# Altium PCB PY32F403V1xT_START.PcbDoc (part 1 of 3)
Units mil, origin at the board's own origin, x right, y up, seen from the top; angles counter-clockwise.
Board outline 1968.43 x 4717 mil, 2 copper layers (Top Layer, Bottom Layer), stack 21 mil thick; 171 components, 201 nets, 720 pads, 402 vias.
Unrouted connection lines stored in the file: 1.
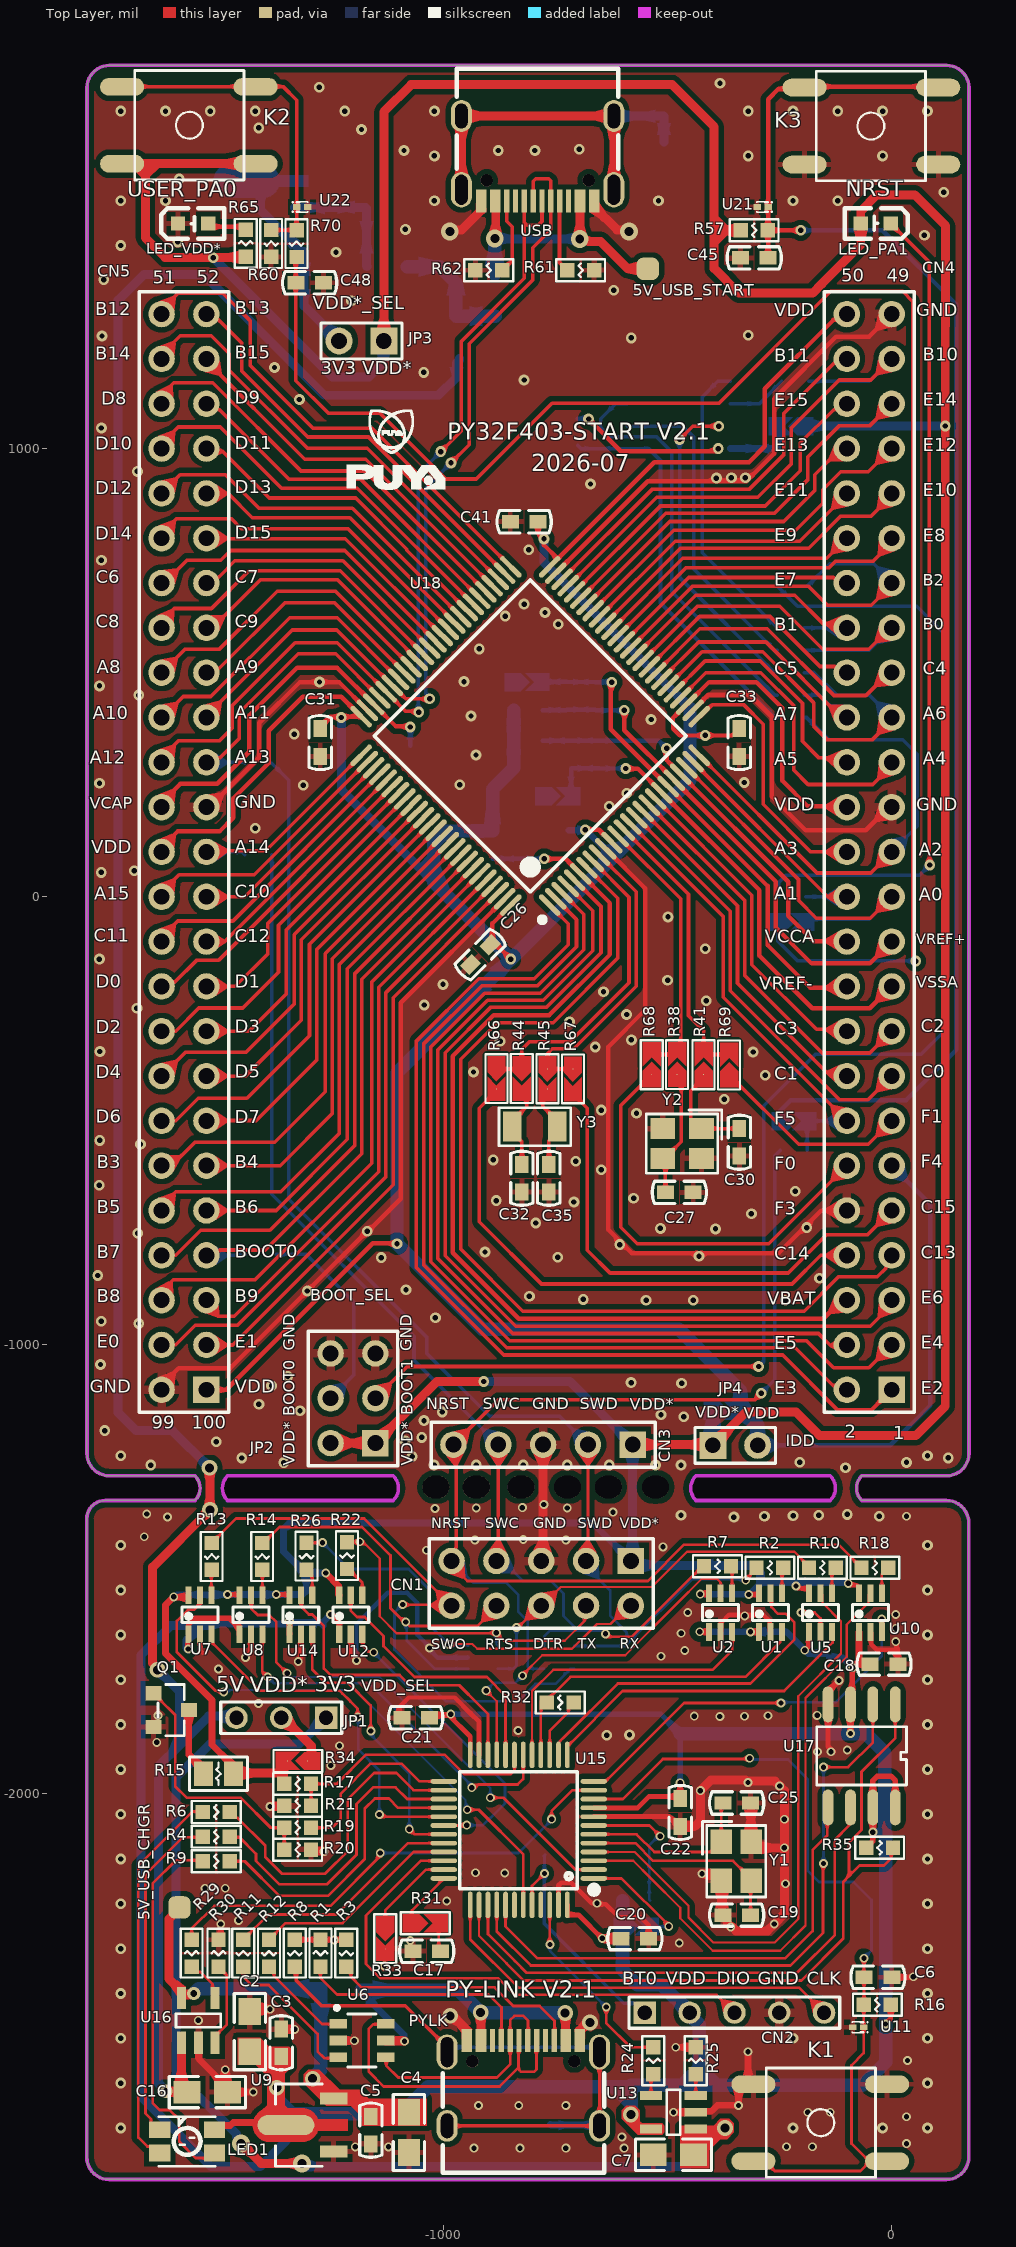
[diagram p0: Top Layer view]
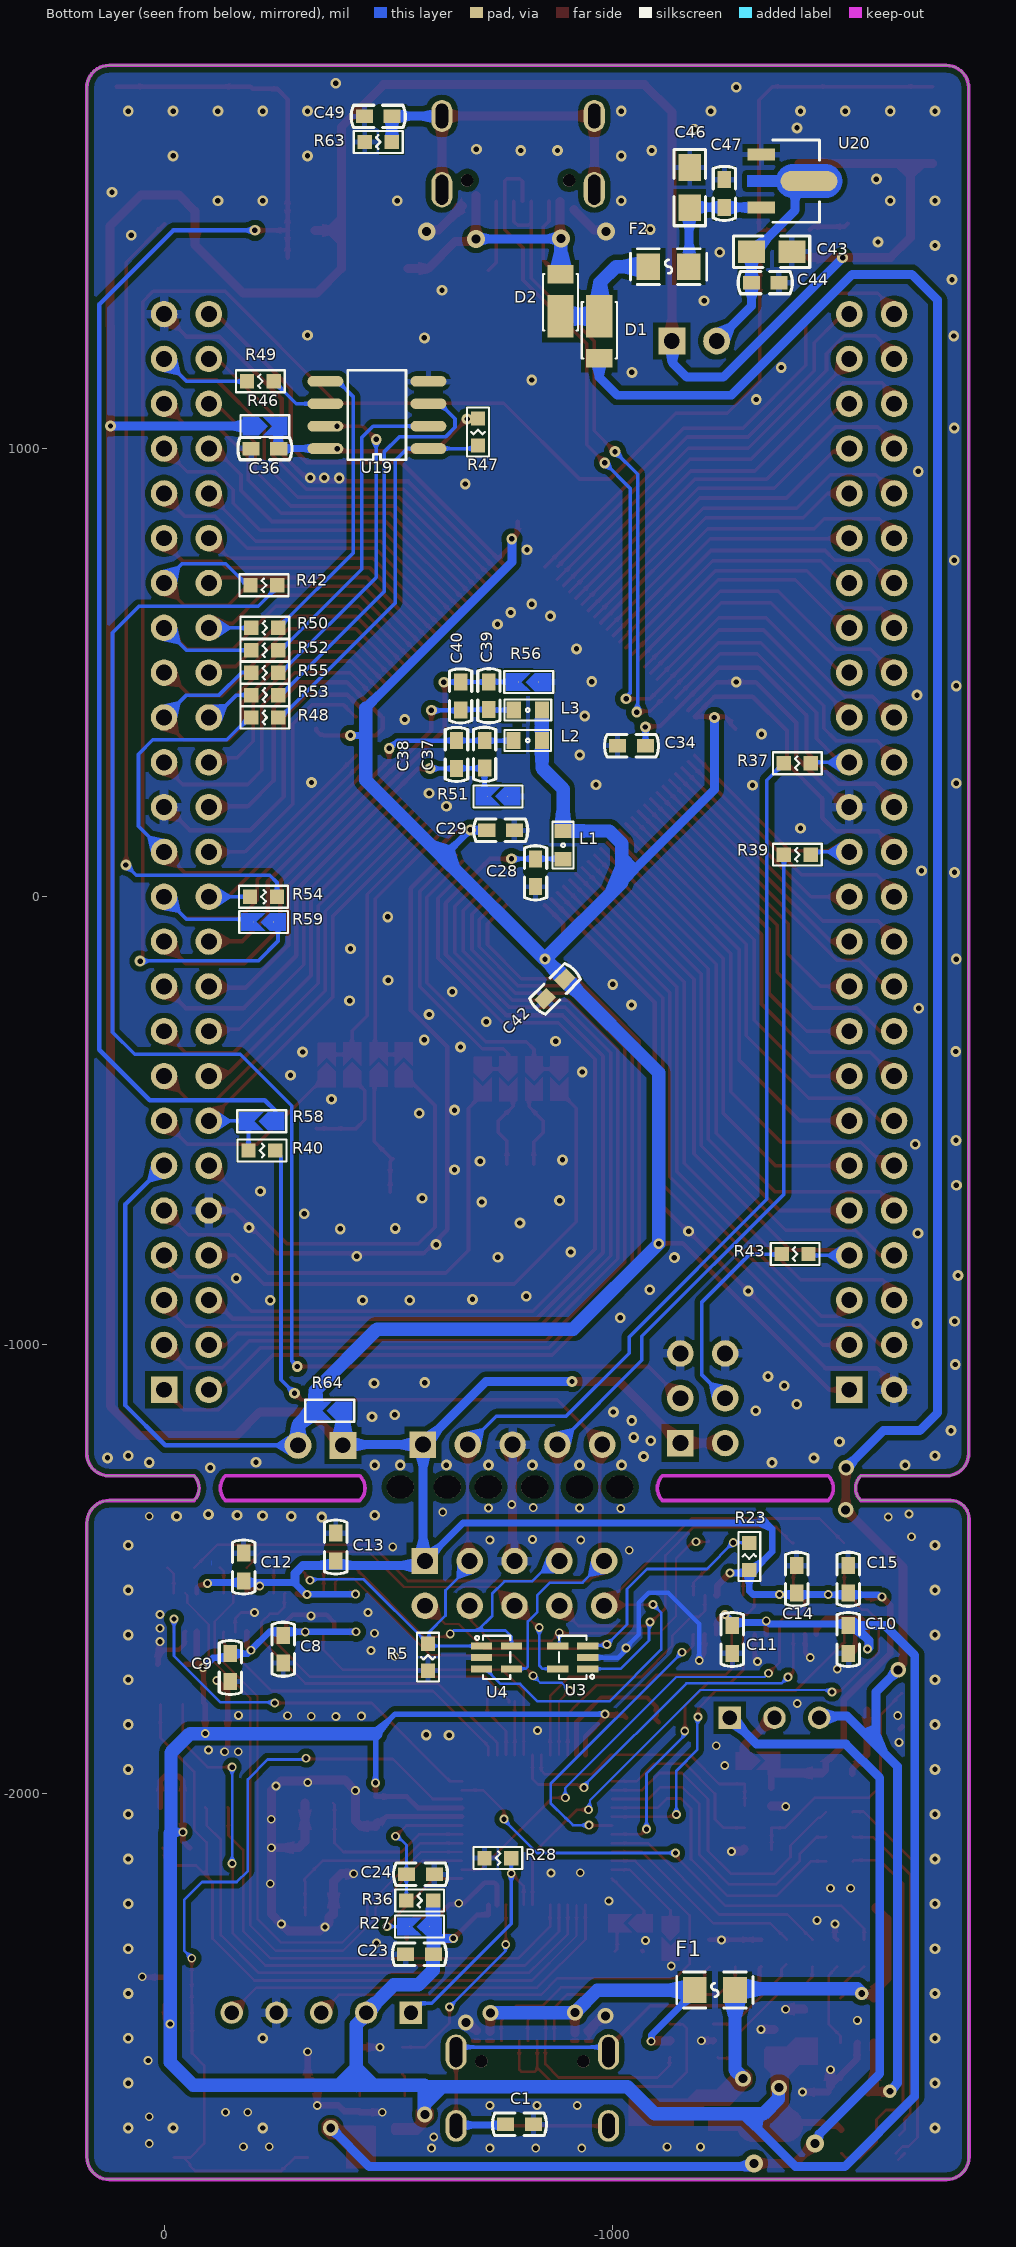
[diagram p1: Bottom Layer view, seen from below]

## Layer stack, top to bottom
Top Solder: solder mask 0.4, Solder Resist, Dk 3.5
Top Layer: signal copper 1.4
Dielectric 2: prepreg 2.8, Composite dielectric, Dk 4.1
Dielectric 1: prepreg 12.6, Composite dielectric, Dk 4.1
Dielectric 3: prepreg 2.8, Composite dielectric, Dk 4.1
Bottom Layer: signal copper 1.4
Bottom Solder: solder mask 0.4, Solder Resist, Dk 3.5

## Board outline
-1796,-2812 ccw(c-1746,-2812) -1746,-2862 122,-2862 ccw(c122,-2812) 172,-2812 172,-1397 ccw(c122,-1397) 122,-1347 -67,-1347 cw(c-39.5,-1319.5) -67,-1292 122.43,-1292 ccw(c122.43,-1242) 172.43,-1242 172.43,1805 ccw(c122.43,1805) 122.43,1855 -1745.43,1855 ccw(c-1745.43,1805) -1795.43,1805 -1795.43,-1242 ccw(c-1745.43,-1242) -1745.43,-1292 -1554.5,-1292 cw(c-1582,-1319.5) -1554.5,-1347 -1755,-1347 ccw(c-1755,-1388) -1796,-1388
cut-out: -437,-1347 cw(c-409.5,-1319.5) -437,-1292 -137,-1292 cw(c-164.5,-1319.5) -137,-1347
cut-out: -1482,-1347 cw(c-1454.5,-1319.5) -1482,-1292 -1112,-1292 cw(c-1139.5,-1319.5) -1112,-1347
cut-out: -1482,-1347 cw(c-1454.5,-1319.5) -1482,-1292 -1112,-1292 cw(c-1139.5,-1319.5) -1112,-1347 -1132,-1347
cut-out: -437,-1347 cw(c-409.5,-1319.5) -437,-1292 -137,-1292 cw(c-164.5,-1319.5) -137,-1347

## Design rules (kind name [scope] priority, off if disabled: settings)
Clearance polygon [InPolygon] p1: gap=12 ignorepadtopadclearanceinfootprint=TRUE
Clearance [All] p2: gap=8 ignorepadtopadclearanceinfootprint=TRUE
HoleToHoleClearance [All] p1: gap=1 allowstackedmicrovias=TRUE
MinimumSolderMaskSliver [All] p1: minsoldermaskwidth=0
PlaneClearance [All] p1: clearance=8
PlaneConnect [All] p1: planeconnectstyle=Direct reliefexpansion=20 reliefentries=4 reliefconductorwidth=10 reliefairgap=10
PolygonConnect [All] p1: thpad.connectstyle=Relief thpad.reliefconductorwidth=20 thpad.reliefentries=4 thpad.polygonreliefangle="90 Angle" thpad.airgapwidth=10 smdpad.connectstyle=Relief smdpad.reliefconductorwidth=12 smdpad.reliefentries=4 smdpad.polygonreliefangle="90 Angle" smdpad.airgapwidth=10 via.connectstyle=Direct via.reliefconductorwidth=10 via.reliefentries=4 via.polygonreliefangle="90 Angle" via.airgapwidth=10
RoutingVias [All] p1: holewidth=28 width=50 viastyle="Through Hole" minholewidth=28 minwidth=50 maxholewidth=28 maxwidth=50
SilkToSilkClearance [All] p1: silktosilkclearance=0
SilkToSolderMaskClearance [IsPad] p1: minsilkscreentomaskgap=0 clearancetoexposedcopper=TRUE
SolderMaskExpansion [All] p1: expansion=4 istentingtop=FALSE
UnRoutedNet [All] p1: checkbadconnections=TRUE
Width [All] p1: maxlimit=100 minlimit=5 preferedwidth=8
23 further rules are at their usual default settings.

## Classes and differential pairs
component class PY32F403V1xT_START: 5V_USB_START C26 C27 C28 C29 C30 C31 C32 C33 C34 C35 C36 C37 C38 C39 C40 C41 C42 C43 C44 C45 C46 C47 C48 C49 CN3 CN4 CN5 D1 D2 F2 "IDD Test" JP2 JP3 JP4 K2 K3 L1 L2 L3 LED_PA1 LED_VDD* PF8 R37 R38 R39 R40 R41 R42 R43 R44 R45 R46 R47 R48 R49 R50 R51 R52 R53 R54 R55 R56 R57 R58 R59 R60 R61 R62 R63 R64 R65 R66 R67 R68 R69 R70 ss U18 U19 U20 U21 U22 USB Y2 Y3
component class PY32F403C1xT_LINK: 5V_USB_CHGR C1 C2 C3 C4 C5 C6 C7 C8 C9 C10 C11 C12 C13 C14 C15 C16 C17 C18 C19 C20 C21 C22 C23 C24 C25 CN1 CN2 F1 JP1 K1 LED1 PYLK Q1 R1 R2 R3 R4 R5 R6 R7 R8 R9 R10 R11 R12 R13 R14 R15 R16 R17 R18 R19 R20 R21 R22 R23 R24 R25 R26 R27 R28 R29 R30 R31 R32 R33 R34 R35 R36 ss U1 U2 U3 U4 U5 U6 U7 U8 U9 U10 U11 U12 U13 U14 U15 U16 U17 Y1

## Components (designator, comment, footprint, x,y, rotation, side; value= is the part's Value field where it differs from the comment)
5V_USB_CHGR "TP_SIN" TP_SIN -1589,-2255 r90 top
5V_USB_START "TP_SIN" TP_SIN -544,1401 r90 top
C1 "4.7nF" C0603 -793,-2739 r0 bottom
C2 "10uF" C0805 -1432,-2532 r270 top
C3 "100nF" C0603 -1362,-2557 r270 top
C4 "10uF" C0805 -1077,-2757 r90 top
C5 "100nF" C0603 -1162,-2752 r90 top
C6 "100nF" C0603 -30.8,-2410.8 r180 top
C7 "10uF" C0805 -487,-2807 r0 top
C8 "100nF" C0603 -266,-1679 r90 bottom value=104
C9 "100nF" C0603 -148.1,-1719.7 r90 bottom value=104
C10 "100nF" C0603 -1526.8,-1657.1 r90 bottom value=104
C11 "100nF" C0603 -1268,-1657.1 r90 bottom value=104
C12 "100nF" C0603 -177.6,-1495.4 r270 bottom value=104
C13 "100nF" C0603 -383.2,-1450.9 r270 bottom value=104
C14 "100nF" C0603 -1411.5,-1522.8 r270 bottom value=104
C15 "100nF" C0603 -1526.5,-1522.8 r270 bottom value=104
C16 "10uF" C0805 -1527,-2667 r180 top
C17 "100nF" C0603 -1037.41,-2352.5 r0 top
C18 "100nF" C0603 -17,-1712 r180 top value=104
C19 "22pF" C0603 -345.88,-2272 r0 top
C20 "100nF" C0603 -573.13,-2324.41 r180 top value=104
C21 "100nF" C0603 -1062,-1832 r0 top value=104
C22 "100nF" C0603 -471.88,-2043 r90 top value=104
C23 "100nF" C0603 -569.9,-2359.7 r180 bottom value=104
C24 "100nF" C0603 -572.5,-2181.2 r0 bottom value=104
C25 "22pF" C0603 -345.88,-2022 r180 top
C26 "100nF" c0603cap -939.9,-151.1 r135 top
C27 "22pF" C0603 -473.8,-659.7 r180 top
C28 "100nF" c0603cap -828.9,22.4 r0 bottom
C29 "100nF" c0603cap -782.1,148.2 r270 bottom
C30 "22pF" C0603 -339.8,-547.7 r90 top
C31 "100nF" c0603cap -1275,375 r0 top
C32 "22pF" C0603 -825,-628 r270 top
C33 "100nF" c0603cap -340,375 r0 top
C34 "100nF" c0603cap -1074.1,337.1 r270 bottom
C35 "22pF" C0603 -765,-628 r90 top
C36 "100nF" C0603 -225,1000 r180 bottom value=104
C37 "1uF" C0603 -715.2,317.8 r90 bottom
C38 "100nF" C0603 -652.6,317.6 r90 bottom
C39 "1uF" C0603 -724.9,448.6 r270 bottom
C40 "100nF" C0603 -661.6,448.2 r270 bottom
C41 "100nF" c0603cap -851,837 r90 top
C42 "10uF" c0603cap -850.5,-227.5 r45 bottom
C43 "10uF" C0805 -1355.9,1439.4 r0 bottom
C44 "100nF" C0603 -1341.5,1370.3 r0 bottom
C45 "100nF" C0603 -306.7,1425.3 r0 top
C46 "10uF" C0805 -1173,1582.3 r270 bottom
C47 "100nF" C0603 -1250.3,1569.4 r270 bottom
C48 "100nF" C0603 -1298.6,1369.9 r180 top
C49 "4.7nF" C0603 -478,1741 r180 bottom
CN1 "2X5P" HDR2X5 -582,-1482 r180 top
CN2 "CON5" CON5 -550.9,-2489.7 r0 top
CN3 "Header 5" HDR1X5 -577.74,-1222.44 r180 top
CN4 "2X25P" HDR2X25 0,-1100 r90 top
CN5 "2X25P" HDR2X25 -1529,-1100 r90 top
D1 "DFLS130L-7" POWERDI-123_L2.8-W1.8-LS3.7-RD -971.3,1248.6 r270 bottom
D2 "DFLS130L-7" POWERDI-123_L2.8-W1.8-LS3.7-RD -884.6,1342.3 r90 bottom
F1 "JK-SMD0805-050-16V" F0805 -1229,-2439.2 r180 bottom
F2 "JK-SMD0805-050-16V" F0805 -1125.7,1406 r180 bottom
JP1 "CON3" CON3 -1262,-1832 r180 top
JP2 "Header 3X2" HDR2X3 -1152,-1219 r90 top
JP3 "CON2" CON2 -1133,1240 r180 top
JP4 "CON2" CON2 -399,-1224 r0 top
K1 "TS-KG02S-AT43F" SW-SMD_4P-L6.0-W6.0-P4.50-LS8.5 -157.4,-2735.5 r180 top
K2 "TS-KG02S-AT43F" SW-SMD_4P-L6.0-W6.0-P4.50-LS8.5 -1566.2,1721.2 r180 top
K3 "TS-KG02S-AT43F" SW-SMD_4P-L6.0-W6.0-P4.50-LS8.5 -47.2,1719.8 r0 top
L1 "GZ1608D601TF" L0603 -890.4,115.2 r90 bottom value=600R@100MHz
L2 "GZ1608D601TF" L0603 -811.6,348.8 r0 bottom value=600R@100MHz
L3 "GZ1608D601TF" L0603 -811.8,416.6 r0 bottom value=600R@100MHz
LED1 "MHPA3528RGBCT" LED-ARRAY-SMD_4P-L3.5-W2.8-TL -1572,-2777 r0 top
LED_PA1 "GREEN" 0603_LED -50,1503 r180 top
LED_VDD* "RED" 0603_LED -1544,1501 r0 top
PYLK "KH-TYPE-C-16P" USB-C-SMD_KH-TYPE-C-16P -821.8,-2647.19 r0 top locked
Q1 "2302" SOT23 -1607.63,-1814.6 r90 top value=SI2302
R1 "5.1K" R0603 -1274.51,-2357.01 r270 top
R2 "27R" R0603 -271.79,-1497 r180 top
R3 "5.1K" R0603 -1217,-2357 r90 top
R4 "680R" R0603 -1507,-2097 r0 top
R5 "1M" R0603 -589.1,-1696.6 r90 bottom
R6 "680R" R0603 -1507,-2042 r0 top
R7 "27R" R0603 -388.61,-1493.9 r180 top
R8 "1M" R0603 -1332,-2357 r90 top
R9 "680R" R0603 -1507,-2152 r0 top
R10 "27R" R0603 -154.65,-1497 r180 top
R11 "27R" R0603 -1447,-2357 r90 top
R12 "27R" R0603 -1389.5,-2357 r90 top
R13 "27R" R0603 -1517.34,-1471.92 r90 top
R14 "27R" R0603 -1404.7,-1471.9 r90 top
R15 "100R" R0805 -1502,-1957 r0 top
R16 "10K" R0603 -32,-2472 r0 top
R17 "20K" R0603 -1325.48,-1979.39 r180 top
R18 "27R" R0603 -37.51,-1497 r180 top
R19 "100R" R0603 -1325.47,-2077.22 r0 top
R20 "100K" R0603 -1325.48,-2126.12 r180 top
R21 "10K" R0603 -1325.47,-2028.31 r0 top
R22 "27R" R0603 -1215.37,-1469.89 r90 top
R23 "4.7K" R0603 -1306,-1472 r270 bottom
R24 "4.7K" R0603 -532,-2597 r270 top
R25 "16K" R0603 -437,-2597 r270 top
R26 "27R" R0603 -1305.8,-1471.3 r90 top
R27 "0R" JP2_SMD -570,-2297.6 r180 bottom
R28 "10K" R0603 -745,-2144.92 r0 bottom
R29 "4.7K" R0603 -1562,-2357 r270 top
R30 "16K" R0603 -1502,-2357 r270 top
R31 "0R" JP2_SMD -1040.79,-2290.25 r180 top
R32 "680R" R0603 -739.54,-1797.63 r0 top
R33 "0R" JP2_SMD -1130.04,-2324.6 r90 top
R34 "0R" JP2_SMD -1325,-1928.2 r0 top
R35 "100K" R0603 -27,-2122 r180 top
R36 "10K" R0603 -570.4,-2239.5 r180 bottom
R37 "100R" R0603 -1413.09,298 r180 bottom
R38 "0R" JP2_SMD -478.8,-374.69 r270 top
R39 "100R" R0603 -1413.09,94 r180 bottom
R40 "0R" R0603 -218.55,-566 r0 bottom
R41 "0R" JP2_SMD -419.8,-374.7 r270 top
R42 "10K" R0603 -223,695 r180 bottom
R43 "10K" R0603 -1408,-797 r180 bottom
R44 "0R" JP2_SMD -825.5,-405.6 r90 top
R45 "0R" JP2_SMD -768,-406 r90 top
R46 "0R" JP2_SMD -224.9,1050.1 r0 bottom
R47 "100K" R0603 -700.5,1037 r90 bottom
R48 "0R" R0603 -225,400 r180 bottom
R49 "0R" R0603 -215,1150 r180 bottom
R50 "0R" R0603 -225,600 r180 bottom
R51 "0R" JP2_SMD -745.1,223.9 r180 bottom
R52 "0R" R0603 -225,550 r180 bottom
R53 "0R" R0603 -225,450 r180 bottom
R54 "1K" R0603 -222,0 r0 bottom
R55 "0R" R0603 -225,500 r180 bottom
R56 "0R" JP2_SMD -813.7,479.1 r180 bottom
R57 "10K" R0603 -306.8,1486.9 r0 top
R58 "0R" JP2_SMD -218,-500.9 r180 bottom
R59 "0R" JP2_SMD -222.3,-56.3 r180 bottom
R60 "1.5K" R0603 -1384.6,1457.7 r90 top
R61 "5.1K" R0603 -694,1398 r0 top
R62 "5.1K" R0603 -899,1398 r0 top
R63 "1M" R0603 -478,1684 r180 bottom
R64 "0R" JP2_SMD -369.8,-1146.6 r180 bottom
R65 "680R" R0603 -1441,1458 r270 top
R66 "0R" JP2_SMD -881.77,-405.67 r90 top
R67 "0R" JP2_SMD -711.1,-406.15 r90 top
R68 "0R" JP2_SMD -535.3,-374.7 r270 top
R69 "0R" JP2_SMD -362.9,-375.25 r270 top
R70 "330R" R0603 -1327.8,1457.3 r90 top
U1 "74LVC1T45DW" SOT363 -270.36,-1597 r0 top
U2 "74LVC1T45DW" SOT363 -381.79,-1597 r0 top
U3 "ESD_6V1" ESD_SOT323-5L -912,-1697 r90 bottom value=ESDALC6V1W5
U4 "ESD_6V1" ESD_SOT323-5L -742,-1697 r270 bottom value=ESDALC6V1W5
U5 "74LVC1T45DW" SOT363 -158.94,-1597 r0 top locked
U6 "USBLC6-2SC6" SOT23-6 -1182,-2552 r90 top
U7 "74LVC1T45DW" SOT363 -1543.45,-1602 r0 top locked
U8 "74LVC1T45DW" SOT363 -1429.74,-1602 r0 top
U9 "LM1117F-3.3" SOT-89-3_L4.5-W2.5-P1.50-LS4.2-BR -1298.2,-2740.6 r0 top
U10 "74LVC1T45DW" SOT363 -47.51,-1597 r0 top
U11 "ESDALC6V1-1U2" ESD_ST0201 -74.7,-2522.3 r180 top
U12 "74LVC1T45DW" SOT363 -1206.88,-1602 r0 top
U13 "MT9700" SOT23-5 -487,-2712 r90 top
U14 "74LVC1T45DW" SOT363 -1318.31,-1602 r0 top
U15 "PY32F403C1xT" LQFP-48_L7.0-W7.0-P0.50-LS9.0-BL -832,-2082 r90 top locked
U16 "MT9700" SOT23-5 -1547,-2507 r0 top
U17 "P25Q64SH" SOP-8P -67,-1917 r180 top value=SST25VF020B
U18 "PY32F403V1xT" LQFP-100_L14.0-W14.0-P0.50-LS16.0-BL -806.52,358.76 r45 top locked
U19 "P25Q64SH" SOP-8P -475,1075 r90 bottom value=SST25VF020B
U20 "LM1117F-3.3" SOT-89-3_L4.5-W2.5-P1.50-LS4.2-BR -1385.9,1596.8 r0 bottom
U21 "ESDALC6V1-1U2" ESD_ST0201 -288,1539 r180 top
U22 "ESDALC6V1-1U2" ESD_ST0201 -1315.3,1539 r0 top
USB "KH-TYPE-C-16P" USB-C-SMD_KH-TYPE-C-16P -790,1647 r180 top
Y1 "24MHz" CRYSTAL-SMD_4P-L3.2-W2.5-BL -346.88,-2152 r270 top
Y2 "24MHz" CRYSTAL-SMD_4P-L3.2-W2.5-BL -467.8,-550.7 r180 top
Y3 "32.768KHz" CRYSTAL-SMD_L3.2-W1.5-1 -796.2,-513.1 r0 top value=X503225MSB2GI

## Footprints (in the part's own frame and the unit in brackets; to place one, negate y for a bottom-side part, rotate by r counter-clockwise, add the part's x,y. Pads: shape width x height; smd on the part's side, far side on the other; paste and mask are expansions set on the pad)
0603_LED [mil]
  rect 31.5x31.5 smd: 1(19,1) 2(-48,1)
  silkscreen extent -86,-33 55,35
C0603 [mil]
  rect 38x30 smd: 1(-31,0) 2(31,0)
  silkscreen extent -60,-25 60,25
c0603cap [mil]
  rect 30x38 smd: 1(0,0) 2(0,-62)
  silkscreen extent -25,-91 25,29
C0805 [mil]
  rect 60x50 smd: 1(-45,0) 2(45,0)
  silkscreen extent -85,-35 85,35
CON2 [mil]
  rect 60x60 hole 35: 1(0,0)
  round 60 hole 35: 2(100,0)
  silkscreen extent -40,-40 140,40
CON3 [mil]
  rect 50x50 hole 32: 1(0,0)
  round 50 hole 32: 2(100,0) 3(200,0)
  silkscreen extent -35,-35 235,35
CON5 [mil]
  rect 50x50 hole 32: 1(0,0)
  round 50 hole 32: 2(100,0) 3(200,0) 4(300,0) 5(400,0)
  silkscreen extent -35,-35 435,35
CRYSTAL-SMD_4P-L3.2-W2.5-BL [mm]
  rect 1.4x1.2 smd: 1(-1.1,-0.85) 2(1.1,-0.85) 3(1.1,0.85) 4(-1.1,0.85)
  silkscreen extent -2.26,-1.91 2.03,1.68
CRYSTAL-SMD_L3.2-W1.5-1 [mm]
  rect 1.05x1.7 smd: 1(-1.275,0) 2(1.275,0)
  silkscreen extent -2.03,-1.08 2.03,1.08
ESD_SOT323-5L [mm]
  rect 0.4x1.2 smd mask+0.05: 1(-0.65,-0.85) 2(0,-0.85) 3(0.65,-0.85) 4(0.65,0.85) 5(-0.65,0.85)
  silkscreen extent -1.23,-1.21 1.23,0.77, body extent -1.15,-1.05 1.15,1.05, height 1.1
ESD_ST0201 [mm]
  rect 0.425x0.33 smd mask+0.05: 1(-0.312,0) 2(0.312,0)
  silkscreen extent -0.55,-0.3 0.33,0.3, body extent -0.34,-0.18 0.34,0.18, height 0.34
F0805 [mm]
  rect 1.335x1.5 smd paste-100 mask+0.051: 1(-1.142,0) 2(1.142,0)
  silkscreen extent -2.16,-1.02 2.16,1.02
HDR1X5 [mm] "Connector; Header; 5 Position"
  rect 1.5x1.5 hole 0.9: 1(0,0)
  round 1.5 hole 0.9: 2(2.54,0) 3(5.08,0) 4(7.62,0) 5(10.16,0)
  silkscreen extent -1.27,-1.27 11.43,1.27
HDR2X3 [mm] "Connector; Header; 3x2 Position"
  rect 1.5x1.5 hole 0.9: 1(0,0)
  round 1.5 hole 0.9: 2(0,2.54) 3(2.54,0) 4(2.54,2.54) 5(5.08,0) 6(5.08,2.54)
  silkscreen extent -1.27,-1.27 6.35,3.81
HDR2X5 [mm] "Connector; Header; 4x2 Position"
  rect 1.5x1.5 hole 0.9: 1(0,0)
  round 1.5 hole 0.9: 2(0,2.54) 3(2.54,0) 4(2.54,2.54) 5(5.08,0) 6(5.08,2.54) 7(7.62,0) 8(7.62,2.54) 9(10.16,0) 10(10.16,2.54)
  silkscreen extent -1.27,-1.27 11.43,3.81
HDR2X25 [mm] "Connector; Header; 25x2 Position"
  rect 1.5x1.5 hole 0.9: 1(0,0)
  round 1.5 hole 0.9: 2(0,2.54) 3(2.54,0) 4(2.54,2.54) 5(5.08,0) 6(5.08,2.54) 7(7.62,0) 8(7.62,2.54) 9(10.16,0) 10(10.16,2.54) 11(12.7,0) 12(12.7,2.54) 13(15.24,0) 14(15.24,2.54) 15(17.78,0) 16(17.78,2.54) 17(20.32,0) 18(20.32,2.54) 19(22.86,0) 20(22.86,2.54) 21(25.4,0) 22(25.4,2.54) 23(27.94,0) 24(27.94,2.54) 25(30.48,0) 26(30.48,2.54) 27(33.02,0) 28(33.02,2.54) 29(35.56,0) 30(35.56,2.54) 31(38.1,0) 32(38.1,2.54) 33(40.64,0) 34(40.64,2.54) 35(43.18,0) 36(43.18,2.54) 37(45.72,0) 38(45.72,2.54) 39(48.26,0) 40(48.26,2.54) 41(50.8,0) 42(50.8,2.54) 43(53.34,0) 44(53.34,2.54) 45(55.88,0) 46(55.88,2.54) 47(58.42,0) 48(58.42,2.54) 49(60.96,0) 50(60.96,2.54)
  silkscreen extent -1.27,-1.27 62.23,3.81
JP2_SMD [mil]
  round 1 smd: 1(21.75,0) 2(-23.03,0.03)
  Top Layer region: -6.25,0 13.75,20 49.75,20 49.75,-20 49.75,-20 13.75,-20
  Top Layer region: -49.77,20.03 -49.77,20.03 3.72,20.03 -16.28,0.03 3.72,-19.98 -49.78,-19.98 -49.78,-19.98
  silkscreen extent -55,-25 54,25
L0603 [mm]
  rect 0.8x0.95 smd mask+0.05: 1(-0.8,0) 2(0.8,0)
  silkscreen extent -1.33,-0.6 1.33,0.6, body extent -0.87,-0.47 0.87,0.47, height 0.95
LED-ARRAY-SMD_4P-L3.5-W2.8-TL [mm]
  rect 1.2x0.95 smd: 1(1.55,0.665) 2(1.55,-0.665) 3(-1.55,-0.665) 4(-1.55,0.665)
  silkscreen extent -1.6,-1.4 1.6,1.4
LQFP-48_L7.0-W7.0-P0.50-LS9.0-BL [mm]
  oval 0.27x1.5 smd mask+0.05: 1(-2.75,-4.25) 2(-2.25,-4.25) 3(-1.75,-4.25) 4(-1.25,-4.25) 5(-0.75,-4.25) 6(-0.25,-4.25) 7(0.25,-4.25) 8(0.75,-4.25) 9(1.25,-4.25) 10(1.75,-4.25) 11(2.25,-4.25) 12(2.75,-4.25) 25(2.75,4.25) 26(2.25,4.25) 27(1.75,4.25) 28(1.25,4.25) 29(0.75,4.25) 30(0.25,4.25) 31(-0.25,4.25) 32(-0.75,4.25) 33(-1.25,4.25) 34(-1.75,4.25) 35(-2.25,4.25) 36(-2.75,4.25)
  oval 1.5x0.27 smd mask+0.05: 13(4.25,-2.75) 14(4.25,-2.25) 15(4.25,-1.75) 16(4.25,-1.25) 17(4.25,-0.75) 18(4.25,-0.25) 19(4.25,0.25) 20(4.25,0.75) 21(4.25,1.25) 22(4.25,1.75) 23(4.25,2.25) 24(4.25,2.75) 37(-4.25,2.75) 38(-4.25,2.25) 39(-4.25,1.75) 40(-4.25,1.25) 41(-4.25,0.75) 42(-4.25,0.25) 43(-4.25,-0.25) 44(-4.25,-0.75) 45(-4.25,-1.25) 46(-4.25,-1.75) 47(-4.25,-2.25) 48(-4.25,-2.75)
  silkscreen extent -3.59,-4.46 3.3,3.34
LQFP-100_L14.0-W14.0-P0.50-LS16.0-BL [mm]
  oval 0.3x1.6 smd: 1(-6,-7.55) 2(-5.5,-7.55) 3(-5,-7.55) 4(-4.5,-7.55) 5(-4,-7.55) 6(-3.5,-7.55) 7(-3,-7.55) 8(-2.5,-7.55) 9(-2,-7.55) 10(-1.5,-7.55) 11(-1,-7.55) 12(-0.5,-7.55) 13(0,-7.55) 14(0.5,-7.55) 15(1,-7.55) 16(1.5,-7.55) 17(2,-7.55) 18(2.5,-7.55) 19(3,-7.55) 20(3.5,-7.55) 21(4,-7.55) 22(4.5,-7.55) 23(5,-7.55) 24(5.5,-7.55) 25(6,-7.55) 51(6,7.55) 52(5.5,7.55) 53(5,7.55) 54(4.5,7.55) 55(4,7.55) 56(3.5,7.55) 57(3,7.55) 58(2.5,7.55) 59(2,7.55) 60(1.5,7.55) 61(1,7.55) 62(0.5,7.55) 63(0,7.55) 64(-0.5,7.55) 65(-1,7.55) 66(-1.5,7.55) 67(-2,7.55) 68(-2.5,7.55) 69(-3,7.55) 70(-3.5,7.55) 71(-4,7.55) 72(-4.5,7.55) 73(-5,7.55) 74(-5.5,7.55) 75(-6,7.55)
  oval 1.6x0.3 smd: 26(7.55,-6) 27(7.55,-5.5) 28(7.55,-5) 29(7.55,-4.5) 30(7.55,-4) 31(7.55,-3.5) 32(7.55,-3) 33(7.55,-2.5) 34(7.55,-2) 35(7.55,-1.5) 36(7.55,-1) 37(7.55,-0.5) 38(7.55,0) 39(7.55,0.5) 40(7.55,1) 41(7.55,1.5) 42(7.55,2) 43(7.55,2.5) 44(7.55,3) 45(7.55,3.5) 46(7.55,4) 47(7.55,4.5) 48(7.55,5) 49(7.55,5.5) 50(7.55,6) 76(-7.55,6) 77(-7.55,5.5) 78(-7.55,5) 79(-7.55,4.5) 80(-7.55,4) 81(-7.55,3.5) 82(-7.55,3) 83(-7.55,2.5) 84(-7.55,2) 85(-7.55,1.5) 86(-7.55,1) 87(-7.55,0.5) 88(-7.55,0) 89(-7.55,-0.5) 90(-7.55,-1) 91(-7.55,-1.5) 92(-7.55,-2) 93(-7.55,-2.5) 94(-7.55,-3) 95(-7.55,-3.5) 96(-7.55,-4) 97(-7.55,-4.5) 98(-7.55,-5) 99(-7.55,-5.5) 100(-7.55,-6)
  silkscreen extent -7.03,-8 6.25,6.25
POWERDI-123_L2.8-W1.8-LS3.7-RD [mm]
  rect 2.4x1.5 smd: 1(-1.187,0)
  rect 1.05x1.5 smd: 2(1.187,0)
  silkscreen extent -2,-1 1.2,1
R0603 [mil]
  rect 32x32 smd: 1(-30,0) 2(30,0)
  silkscreen extent -55,-24 54,25
R0805 [mm]
  rect 1.1x1.4 smd: 1(-0.85,0) 2(0.85,0)
  silkscreen extent -1.65,-0.95 1.65,0.95
SOP-8P [mil]
  oval 24x80 smd: 1(-75,-115) 2(-25,-115) 3(25,-115) 4(75,-115) 5(75,115) 6(25,115) 7(-25,115) 8(-75,115)
  silkscreen extent -100,-65 100,65
SOT23 [mm]
  rect 0.8x0.9 smd: 1(0.95,1) 2(-0.95,1) 3(0,-1)
  silkscreen extent -1.45,-0.75 1.45,0.75
SOT23-5 [mil]
  rect 20x50 smd: 1(-37.5,-50) 2(0,-50) 3(37.5,-50) 4(37.5,50) 5(-37.5,50)
  silkscreen extent -50,-15 50,15
SOT23-6 [mm]
  rect 0.55x1 smd: 1(0.95,1.35) 2(0,1.35) 3(-0.95,1.35) 4(-0.95,-1.35) 5(0,-1.35) 6(0.95,-1.35)
  silkscreen extent -1.5,-0.8 1.96,1.52
SOT363 [mm]
  rect 0.35x1 smd: 1(-0.65,-1.1) 2(0,-1.1) 3(0.65,-1.1) 4(0.65,1.1) 5(0,1.1) 6(-0.65,1.1)
  silkscreen extent -1.02,-0.45 1.02,0.45, body extent -1,-1.1 1,1.16, height 1
SOT-89-3_L4.5-W2.5-P1.50-LS4.2-BR [mm]
  rect 1.575x0.672 smd: 1(1.356,-1.5) 3(1.356,1.5)
  oval 3.226x1.14 smd: 2(-1.356,0)
  Top Layer region: -2.283,0.95 -0.429,0.95 -0.384,0.949 -0.34,0.946 -0.296,0.94 -0.252,0.933 -0.208,0.924 -0.165,0.912 -0.123,0.899 -0.081,0.884 -0.04,0.866 0,0.847 0.04,0.826 0.078,0.803 0.115,0.779 0.151,0.752 0.185,0.724 0.219,0.695 0.251,0.664 0.281,0.631 0.31,0.597 0.337,0.562 0.362,0.525 0.386,0.488 0.408,0.449 0.428,0.409 0.447,0.33 2.144,0.33 2.144,-0.33 0.447,-0.33 0.428,-0.409 0.408,-0.449 0.386,-0.488 0.362,-0.526 0.337,-0.562 0.31,-0.597 0.281,-0.631 0.251,-0.664 0.219,-0.695 0.185,-0.725 0.151,-0.753 0.115,-0.779 0.078,-0.804 0.04,-0.827 0,-0.848 -0.04,-0.867 -0.081,-0.884 -0.123,-0.899 -0.165,-0.913 -0.208,-0.924 -0.252,-0.934 -0.296,-0.941 -0.34,-0.946 -0.384,-0.949 -0.429,-0.95 -2.283,-0.95 -2.328,-0.949 -2.372,-0.946 -2.416,-0.941 -2.46,-0.934 -2.504,-0.924 -2.547,-0.913 -2.589,-0.899 -2.631,-0.884 -2.672,-0.867 -2.713,-0.848 -2.752,-0.827 -2.79,-0.804 -2.827,-0.779 -2.863,-0.753 -2.898,-0.725 -2.931,-0.695 -2.963,-0.664 -2.993,-0.631 -3.022,-0.597 -3.049,-0.562 -3.075,-0.526 -3.098,-0.488 -3.12,-0.449 -3.141,-0.409 -3.159,-0.369 -3.175,-0.327 -3.189,-0.285 -3.202,-0.242 -3.212,-0.199 -3.22,-0.155 -3.227,-0.111 -3.231,-0.067 -3.233,-0.022 -3.233,0.022 -3.231,0.067 -3.227,0.111 -3.22,0.155 -3.212,0.199 -3.202,0.242 -3.189,0.285 -3.175,0.327 -3.159,0.369 -3.141,0.409 -3.12,0.449 -3.098,0.488 -3.075,0.525 -3.049,0.562 -3.022,0.597 -2.993,0.631 -2.963,0.664 -2.931,0.695 -2.898,0.724 -2.863,0.752 -2.827,0.779 -2.79,0.803 -2.752,0.826 -2.713,0.847 -2.672,0.866 -2.631,0.884 -2.589,0.899 -2.547,0.912 -2.504,0.924 -2.46,0.933 -2.416,0.94 -2.372,0.946 -2.328,0.949 -2.283,0.95
  silkscreen extent -1.95,-2.33 0.7,2.33
SW-SMD_4P-L6.0-W6.0-P4.50-LS8.5 [mm]
  oval 2.5x1 smd: 1(-3.734,2.177) 2(3.835,2.177) 3(-3.734,-2.184) 4(3.835,-2.184)
  silkscreen extent -3.08,-3.1 3.12,3.09, body extent -4.48,-3 4.52,3, height 8.95
TP_SIN [mil]
  rrect60% 50x50 smd: 1(0,0)
USB-C-SMD_KH-TYPE-C-16P [mm]
  oval 1.2x2 hole 0.7 slot 1.7 at 90 deg: 1(-4.32,1.765) 2(4.32,1.765)
  oval 1.2x1.8 hole 0.7 slot 1.4 at 90 deg: 3(-4.32,-2.415) 4(4.32,-2.415)
  rect 0.3x1.3 smd: A1(-3.35,2.415) A4(-2.55,2.415) A5(-1.25,2.415) A6(-0.25,2.415) A7(0.25,2.415) A8(1.25,2.415) A9(2.55,2.415) A12(3.35,2.415) B1(3.05,2.415) B4(2.25,2.415) B5(1.75,2.415) B6(0.75,2.415) B7(-0.75,2.415) B8(-1.75,2.415) B9(-2.25,2.415) B12(-3.05,2.415)
  round 0.7 hole 0.7 unplated: ""(-2.89,1.235) ""(2.89,1.235)
  silkscreen extent -4.57,-5.08 4.57,0.57

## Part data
C1 C3 C5 C6 C17 C19 C25 C26 C27 C28 C29 C30 C31 C33 C34 C38 C40 C41 C42 C44 C45 C47 C48 C49: library part C0603
C2 C4 C7 C16 C37 C39 C43 C46: library part C0805
C8 C9 C10 C11 C12 C13 C14 C15 C18 C20 C21 C22 C23 C24 C36: library part 贴片高压陶瓷电容, "Capacitor (Semiconductor SIM Model)"
C32 C35: library part Cap, "Capacitor"
CN1: Color=黑色, Current Rating (Max)=-, JLCPCB Part Class="Extended Part", LCSC Part Name="间距:2.54mm 2x5P 直插 方针", Manufacturer=XFCN(兴飞), Manufacturer Part=PZ254V-12-10P, Operating Temperature Range=-40℃~+105℃
CN3: "Header, 5-Pin"
CN4 CN5: library part "Header 25X2", "Header, 25-Pin, Dual row"
D1 D2: Average Rectified Current (Io)=1A, Forward Voltage (Vf@If)=310mV@1A, JLCPCB Part Class="Extended Part", LCSC Part Name="电压:30V 电流:1A", Manufacturer=DIODES(美台), Reverse Voltage (Vr)=30V
F1 F2: Current - Max=100A, Hold Current=500mA, JLCPCB Part Class="Extended Part", LCSC Part Name="6V 0.5A 贴片自恢复", Manufacturer=JK(金科), Operating Temperature=-40℃~+85℃, Power Dissipation=600mW, Resistance - Initial (Ri) (Min)=150mΩ, Resistance - Post Trip (R1) (Max)=850mΩ, Trip Current=1A, Voltage - Max=6V
JP2: "Header, 3-Pin, Dual row"
JP3 JP4: library part CON2_DIP
K1 K2 K3: Actuator/Cap Color=黑色, Contact Current=50mA, Insulation Resistance=100MΩ, JLCPCB Part Class=扩展库, LCSC Part Name="6*6*4.3mm 立贴 轻触开关", Manufacturer=HANBO(汉博), Operating Force=250gf, Voltage Rating (DC)=12V
L1 L2 L3: "SMD Chip ferrite bead, 600R@100MHz +/-25%, 350mA, 500mohm DC, 0603, T=0.8mm", Manufacturer=TAI-TECH, Manufacturer_Part_Number=FCM1608KF-601T03
LED1: JLCPCB Part Class=扩展库, LCSC Part Name=RGB三色, Manufacturer=MEIHUA(美华)
LED_PA1 LED_VDD*: library part PDI-E803_Dup1
PYLK USB: BOM_JLCPCB Part Class="Extended Part", BOM_Manufacturer="Shenzhen Kinghelm Elec"
Q1: library part "MOSFET N", "MOSFET N"
R1 R2 R3 R4 R5 R6 R7 R8 R9 R10 R11 R12 R13 R14 R16 R17 R18 R19 R20 R21 R22 R23 R24 R26 R27 R28 R29 R31 R32 R33 R34 R35 R36 R37 R38 R39 R40 R41 R42 R43 R44 R45 R46 R47 R48 R49 R50 R51 R52 R53 R54 R55 R56 R57 R58 R59 R60 R61 R62 R63 R64 R65 R66 R67 R68 R69 R70: library part R0603
R15: library part R0805
R25 R30: library part R0603_7, "0603WAF1602T5E 16KΩ(1602) ±1%"
U3 U4: library part ESDALC6V1W5, "Dual Transil array for ESD protection", Manufacturer=STMICROELECTRONICS
U11 U21 U22: "ESD protection 6V1", Manufacturer=STMICROELECTRONICS
U15: "LQFP48", BOM_Manufacturer=PUYA(普冉)
U17 U19: library part SST25VF010, "SST25VF010"
U18: "LQFP100", BOM_Manufacturer=PUYA(普冉)
Y1 Y2: library part ABM8AIG-24.000MHZ-82Z-T, "±20ppm , 12.5pF , T_use: -40°C~125°C", Equivalent Series Resistance (ESR)=50Ω, External load capacitor=8pF, Frequency Stability(Full temperature range)=±50ppm, JLCPCB Part Class="Extended Part", LCSC Part Name="24MHz ±20ppm 8pF", Manufacturer=ABRACON, Normal temperature Frequency Tolerance=±20ppm, Operating Temperature=-40℃~+125℃
Y3: library part SC-32S32.768kHz20PPM12.5pF, "Crystal"

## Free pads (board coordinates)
  oval 60x50 hole 50 slot 60 at 0 deg unplated: 1(-1017,-1317) 1(-927,-1317) 1(-827,-1317) 1(-723.45,-1317) 1(-632,-1317) 1(-527,-1317)

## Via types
v1: diameter 24, hole 12, Top Layer to Bottom Layer, tented both sides, 230 vias
v2: diameter 19.68, hole 11.81, Top Layer to Bottom Layer, tented both sides, 116 vias
v3: diameter 19.68, hole 11.81, Top Layer to Bottom Layer, 37 vias
v4: diameter 35, hole 20, Top Layer to Bottom Layer, tented both sides, 11 vias
v5: diameter 40, hole 20, Top Layer to Bottom Layer, tented both sides, 6 vias
v6: diameter 30, hole 15, Top Layer to Bottom Layer, tented both sides, 2 vias

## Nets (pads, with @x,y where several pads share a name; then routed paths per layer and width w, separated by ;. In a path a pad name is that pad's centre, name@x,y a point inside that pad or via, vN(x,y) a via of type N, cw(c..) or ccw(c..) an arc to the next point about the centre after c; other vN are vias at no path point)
3.3V_OUT_EN: R24.1 U15.46 | length 442.6
  Top Layer w6: U15.46@-763.1,-2249.32 -762.75,-2249.67 -762.75,-2337.25 v2(-762.4,-2337.6) ; v2(-637,-2477) -637,-2512.6 -582.6,-2567 R24.1@-532,-2567
  Bottom Layer w6: v2(-762.4,-2337.6) -762.08,-2337.92 -762.08,-2351.92 v2@-637.32,-2476.68
3V3: C43.2 C44.2 JP3.2 U20.2 | length 455.4
  Bottom Layer w20: U20.2@-1439.3,1596.81 -1419.72,1596.81 -1408.23,1585.31 -1408.23,1531.73 -1315.9,1439.4 C43.2@-1310.9,1439.4 -1311.1,1439.2 -1311.1,1374.5 -1311.1,1318.39 JP3.2@-1233.78,1241.07
3V3_PYLK: C2.2 C3.2 C8.2 C9.2 C10.2 C11.2 C18.2 C20.2 C21.2 C22.2 C23.2 CN2.2 LED1.1 R16.2 R27.1 R35.2 R36.2 U1.1 U2.1 U5.1 U7.1 U8.1 U9.2 U10.1 U12.1 U13.5 U14.1 U15.9 U15.24 U15.48 U17.3 U17.7 U17.8 | length 7988.2
  Top Layer w10: v2(-1251.84,-1601.37) -1247.58,-1601.37 -1232.47,-1616.48 U12.1@-1232.47,-1645.31 ; C21.2@-1031,-1832 C21.2@-1026.34,-1827.34 ; C22.2@-472,-2007.88 v2(-472,-1977) ; v2(-13.6,-2514.9) -13.6,-2514.6 -2,-2503 R16.2@-2,-2472
  Top Layer w11: v2@-987,-1827 -940.27,-1873.73 U15.24@-940.27,-1914.68 ; U15.48@-723.73,-2249.32 -723.73,-2271.39 -723.55,-2271.58 -698.77,-2271.58 -643.35,-2327 v2@-641.88,-2327 ; U15.9@-664.68,-2032.79 -566.61,-2032.79 -541.7,-2007.88 C22.2@-472,-2007.88
  Top Layer w12: v3(-1569.65,-1678.34) -1569.04,-1677.73 U7.1@-1569.04,-1645.31 -1569.04,-1624.13 -1555.04,-1610.12 -1477.19,-1610.12 -1455.33,-1631.99 U8.1@-1455.33,-1645.31 ; U14.1@-1343.9,-1645.31 -1343.01,-1644.42 -1343.88,-1643.54 v2(-1343.88,-1615.61) ; C21.2@-1026.34,-1827.34 -1025.01,-1826.01 -986.01,-1826.01 v2(-983.72,-1823.72) ; v2(-428.27,-1639.97) -427.94,-1640.31 U2.1@-407.38,-1640.31 ; v2(-315,-1640.1) -314.79,-1640.31 U1.1@-295.95,-1640.31 ; v3(-193.99,-1680.98) -184.53,-1671.52 U5.1@-184.53,-1640.31 -185.42,-1641.2 U5.1@-185.2,-1641.42 ; v2(-92,-1867) U17.3@-92,-1802 -87.99,-1797.99 -87.99,-1720.75 v2(-87.13,-1719.89) ; -79.24,-1712 C18.2@-48,-1712 ; R35.2@-57,-2122 -42,-2107 v2(-42,-2087) U17.7@-42,-2032 -42,-1972 -32,-1962 -2,-1962 8,-1972 U17.8@8,-2032
  Top Layer w15: LED1.1@-1510.98,-2750.82 -1501.85,-2741.68 -1475.97,-2741.68 -1469.17,-2734.89 -1357.31,-2734.89 U9.2@-1351.59,-2740.61 ; v2(-87.13,-1719.89) -79.24,-1712 -73.1,-1705.86 U10.1@-73.1,-1640.31
  Top Layer w20: v2@-642.13,-2324.41 C20.2@-604.13,-2324.41
  Bottom Layer w11: -601.6,-2324 -600.9,-2324.7
  Bottom Layer w12: v2(-983.72,-1823.72) -515.28,-1823.72 -472,-1867 ; v2(-472,-1977) -472,-1872 ; v2(-42,-2087) -12.35,-2087
  Bottom Layer w15: C10.2@-1523.36,-1622.66 -1350.93,-1622.66 v2(-1343.88,-1615.61) -1340.08,-1619.4 -1274.7,-1619.4 C11.2@-1268,-1626.1 -1268,-1617.53 v2(-1251.84,-1601.37) v2@-1253.44,-1599.78 ; v2(-428.27,-1639.97) -235,-1639.97 v3(-193.99,-1680.98) -186.27,-1688.7 C9.2@-148.1,-1688.7 ; C9.2@-138.68,-1698.12 -108.9,-1698.12 v2(-87.13,-1719.89)
  Bottom Layer w20: v3(-1569.65,-1678.34) -1572.53,-1675.45 -1572.53,-1658.88 C10.2@-1539.75,-1626.1 ; C10.2@-1526.8,-1626.1 -1547.6,-1626.1 ; C10.2@-1526.8,-1617.8 -1539.3,-1617.8 -1547.6,-1626.1 ; -1291.7,-2715.75 -1409.12,-2833.16 -1518.44,-2833.16 -1675,-2676.6 -1675,-1692.32 -1608.78,-1626.1 -1547.6,-1626.1 ; v2(-645.61,-2324) -601.6,-2324
  Bottom Layer w30: v4(-1372,-2657) -1371.04,-2657.96 -1371.04,-2682.09 -1337.39,-2715.75 -1291.7,-2715.75 -1094.86,-2715.75 -1033.8,-2654.68 -581.04,-2654.68 ; R36.2@-600.4,-2239.5 -600.4,-2288.95 R27.1@-591.75,-2297.6 -600.9,-2306.75 -600.9,-2324.7 C23.2@-600.9,-2359.7 -600.26,-2359.7 -600.26,-2395.14 -567.5,-2427.9 -512.7,-2427.9 CN2.2@-450.9,-2489.7 ; v4(-582,-2717) -581.04,-2716.04 -581.04,-2654.68 ; -472,-1867 v2(-92,-1867) -58.04,-1867 -15.62,-1909.42 -15.62,-2087 -13.6,-2089.02 v2(-13.6,-2514.9) -13.6,-2600.45 -65.15,-2652 -428.9,-2652 ; CN2.2@-448.82,-2493.88 -448.82,-2497.19 -428.9,-2517.11 -428.9,-2652 ; -581.04,-2654.68 -581.04,-2652 -428.9,-2652
3V3_USB_PYLK: C7.2 JP1.1 U13.1 | length 2404.2
  Top Layer w20: v5@-1451.2,-2782 -1406.97,-2826.23 v5(-1316.04,-2826.23)
  Bottom Layer w20: v5(-1452,-2782) -1452,-2776.59 -1461.73,-2766.86 -1461.73,-2761.02 -1596.9,-2625.84 -1596.9,-1966.14 -1521.4,-1890.64 -1322.4,-1890.64 -1278.76,-1847 -1277,-1847 -1263.76,-1833.76 JP1.1@-1263.76,-1832 ; v5(-1316.04,-2826.23) -1309.18,-2833.09 -458.09,-2833.09 v4(-372,-2747) v4@-370.22,-2748.78
5V: D1.1 D2.1 F2.1 | length 285.1
  Bottom Layer w30: F2.1@-1080.72,1406 -1008.4,1406 -972.42,1370.02 -972.42,1296.47 D1.1@-971.3,1295.35 -884.8,1295.35 D2.1@-884.6,1295.55
5V_OUT_EN: R29.1 U15.11 | length 1065.3
  Top Layer w6: R29.1@-1562,-2327 -1562,-2302 -1511.35,-2251.35 -1252.58,-2251.35 -1141.08,-2139.84 v2(-1141.08,-2133.58) ; v2(-758.73,-2057.93) -758.73,-2040.13 -712.02,-1993.42 U15.11@-664.68,-1993.42
  Bottom Layer w6: v2(-1141.08,-2133.58) -832.59,-2133.58 -758.73,-2059.71 v2(-758.73,-2057.93)
5V_USB_CHGR: 5V_USB_CHGR.1 C4.2 C5.2 F1.2 U9.3 U16.5 | length 748.2
  Top Layer w20: 5V_USB_CHGR.1@-1589,-2255 -1589,-2257.71 -1612.6,-2281.31 -1612.6,-2413.9 -1584.5,-2442 U16.5@-1584.5,-2448.91 ; U16.5@-1584.5,-2457 U16.5@-1584.5,-2448.91 ; v6(-1557,-2447) -1558.91,-2448.91 U16.5@-1584.5,-2448.91
  Bottom Layer w30: v6(-1557,-2447) -1546.61,-2436.61 -1273.98,-2436.61 -1273.98,-2617.63 -1292,-2635.65 v4(-1292,-2637) v4@-1292.96,-2636.04
5V_USB_PYLK: C16.2 D1.2 JP1.3 U16.1 | length 5496.6
  Top Layer w20: v4(-1638,-1725) -1638,-1720.94 -1648.9,-1710.04 -1648.9,-1495.76 v4(-1521,-1367.86) -1521.11,-1367.75 -1521.11,-1274.92 v4(-1522,-1274.03) ; v6(-1619.61,-2665.18) -1618.7,-2666.09 -1572.91,-2666.09 C16.2@-1572,-2667 ; U16.1@-1584.5,-2557.31 -1584.5,-2572 -1584.81,-2572.31 -1584.81,-2652 C16.2@-1572,-2652
  Bottom Layer w20: v4(-1638,-1725) -1588.97,-1774.03 -1588.97,-1893 ; v6(-1619.61,-2665.18) -1622.08,-2664.68 -1625.79,-2660.97 -1627.19,-2659.57 -1636.08,-2646.23 -1636.08,-1940.11 -1588.97,-1893 ; v4(-1522,-1274.03) -1605.03,-1191 -1686,-1191 -1726,-1151 -1726,1331 -1668.1,1388.9 -1535.7,1388.9 -1265.76,1118.96 -1011.44,1118.96 -970.8,1159.6 -970.8,1191.18 -964.2,1197.78 D1.2@-964.2,1201.55 ; JP1.3@-1462,-1832 -1465.82,-1828.18 -1524.15,-1828.18 -1588.97,-1893
5V_USB_START: 5V_USB_START.1 D2.2 USB.A4 USB.A9 USB.B4 USB.B9 | length 628.5
  Top Layer w20: v5(-885.61,1468.53) -883.43,1470.71 USB.B4@-883.43,1551.35 ; v5(-695.98,1467.66) -692.15,1463.83 -678.01,1463.83 -676.65,1462.47 -649.92,1462.47 -589.07,1401.62 5V_USB_START.1@-544.62,1401.62 ; v5@-695.66,1467.98 USB.B9@-695.66,1564.56
  Bottom Layer w20: v5(-885.61,1468.53) -885.18,1468.09 -696.42,1468.09 v5(-695.98,1467.66)
  Bottom Layer w30: D2.2@-885.61,1389.05 v5(-885.61,1468.53)
AD_TVDD: R17.1 R21.2 U15.19 | length 586.3
  Top Layer w6: R21.2@-1295.48,-2028.3 R17.1@-1295.48,-1979.39 -1238.21,-1979.39 -1173.03,-1914.21 -997.34,-1914.21 -953.41,-1958.14 -850.14,-1958.14 -841.84,-1949.83 U15.19@-841.84,-1914.68
BOOT0: CN5.7 R43.2 U18.94 | length 1269.3
  Top Layer w8: CN5.7@-1529,-800 -1519.23,-790.23 -1500.85,-790.23 -1498.79,-788.17 -1397.52,-788.17 -1182.41,-573.06 -1182.41,-184.16 U18.94@-933.19,65.06
  Bottom Layer w8: CN5.7@-1529,-800 -1444.5,-800 R43.2@-1442.5,-798
DIR_RESET: U10.5 U15.3 | length 1394.4
  Top Layer w5: U15.3@-664.68,-2150.9 -576.34,-2150.9 -536.97,-2190.27 -471.78,-2255.45 -471.78,-2279.23 -399.22,-2351.78 -248.88,-2351.78 -192.47,-2295.37 -192.47,-1787.96 -100.03,-1695.53 -100.03,-1623.55 -51.9,-1575.41 -51.9,-1558.08 U10.5@-47.51,-1553.69
DIR_RTCK_DTR: U5.5 U15.4 | length 1362.6
  Top Layer w5: U15.4@-664.68,-2131.21 -573.31,-2131.21 -533.94,-2170.58 -453.57,-2250.95 -453.57,-2277.51 -397.91,-2333.17 -261.05,-2333.17 -208.47,-2280.59 -208.47,-1783.68 -113.03,-1688.24 -113.03,-1616.91 -154.55,-1575.4 -154.55,-1558.08 U5.5@-158.94,-1553.69
DIR_TCK_SWCLK: U2.5 U15.21 | length 808
  Top Layer w5: v2(-904.88,-1771.33) -881.21,-1795 U15.21@-881.21,-1914.68 ; v3(-823.51,-1737.87) -823.51,-1736.43 -779.67,-1692.59 -594.66,-1692.59 -480.29,-1578.21 -423.62,-1521.54 -389.81,-1521.54 -381.79,-1529.57 U2.5@-381.79,-1553.69
  Bottom Layer w5: v2(-904.88,-1771.33) -887.39,-1753.84 -839.48,-1753.84 v3(-823.51,-1737.87)
DIR_TDI_VCP_TX: U12.5 U15.20 | length 603.7
  Top Layer w6: U12.5@-1206.88,-1558.69 -1206.88,-1593.23 -1193.08,-1607.02 -1176.03,-1607.02 -1133.75,-1649.3 -1133.75,-1672.08 -1064.89,-1740.94 -903.36,-1740.94 -861.53,-1782.76 U15.20@-861.53,-1914.68
DIR_TDO_SWO: U7.5 U15.43 | length 1242.4
  Top Layer w6: U7.5@-1543.45,-1558.69 -1543.45,-1577.27 -1557.06,-1590.87 -1570.03,-1590.87 -1594.86,-1615.7 -1594.86,-1685.62 -1509.01,-1771.48 -1493.07,-1771.48 v3(-1490.45,-1774.1) ; v2(-947,-2037) -921.31,-2037 -822.16,-2136.15 U15.43@-822.16,-2249.32
  Bottom Layer w5: v3(-1490.45,-1774.1) -1485.95,-1769.59 -1196.79,-1769.59 -950.64,-2015.75 -950.64,-2033.36 v2(-947,-2037)
DIR_TMS_SWDIO: U1.5 U15.14 | length 784.3
  Top Layer w6: U15.14@-743.42,-1914.68 -743.42,-1888.01 -740.05,-1884.64 -740.05,-1883.71 -730.49,-1874.15 -729.56,-1874.15 -610.87,-1755.46 -315.2,-1755.46 -217.6,-1657.87 -217.6,-1618.64 -236.22,-1600.02 -253.21,-1600.02 -268.48,-1584.75 -268.48,-1555.58 U1.5@-270.36,-1553.69
DIR_TRST_RTS: U8.5 U15.2 | length 1100.7
  Top Layer w6: U8.5@-1429.74,-1558.69 -1429.15,-1559.28 -1429.15,-1587.76 -1414.47,-1602.44 -1388.86,-1602.44 -1373.06,-1618.24 -1373.06,-1708.21 v2(-1348.94,-1732.33) ; v2(-895.48,-2010.32) -866.28,-2010.32 -706.02,-2170.58 U15.2@-664.68,-2170.58
  Bottom Layer w5: v2(-1348.94,-1732.33) -1340.67,-1740.59 -1143.41,-1740.59 -895.48,-1988.52 v2(-895.48,-2010.32)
